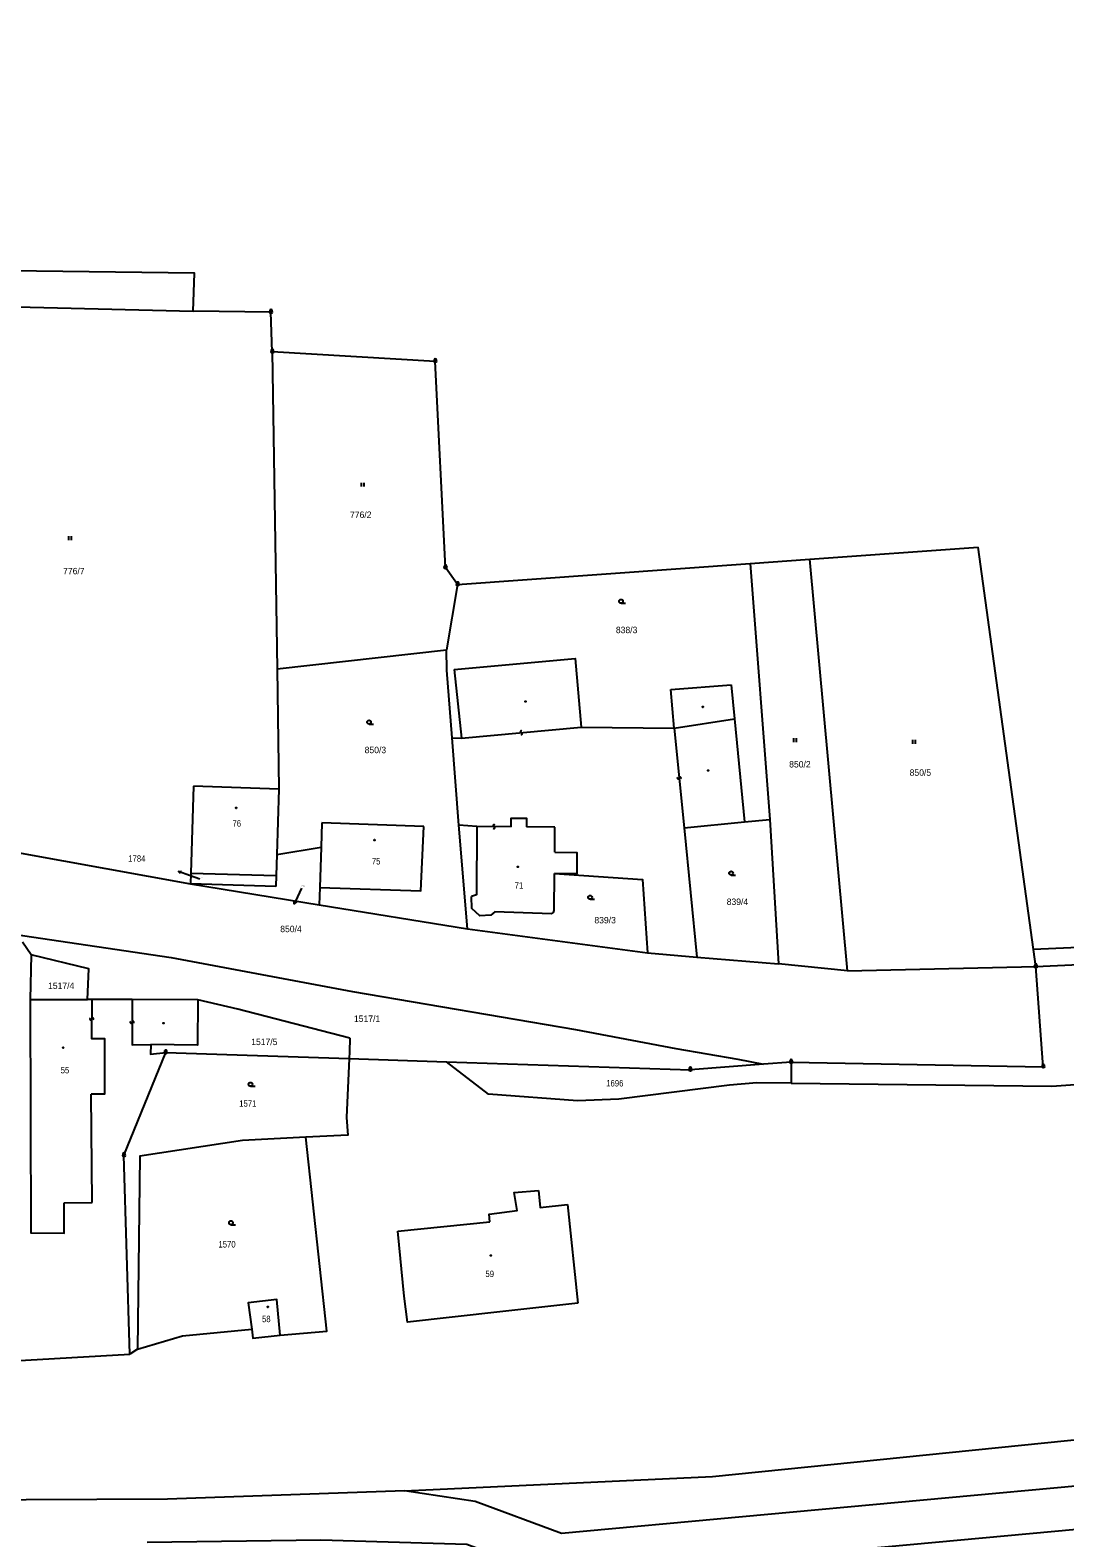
# Model space of a CAD drawing. Extents: x -873052 to -871788, y -1075760 to -1074911.
# Drawn here: x -872787.8 to -872666.9, y -1075585.9 to -1075409.8 of the extents above; entities that cross this region are included whole.
import ezdxf
from ezdxf.enums import TextEntityAlignment as Align

# ---------------------------------------------------------------- set-up
doc = ezdxf.new("R2010")
doc.units = 0
doc.header["$LTSCALE"] = 0.3
for name, color, linetype, lineweight in [('1', 7, 'Continuous', 25), ('16', 7, 'Continuous', 25), ('24', 7, 'Continuous', 25), ('25', 7, 'Continuous', 25), ('4', 7, 'Continuous', 25)]:
    doc.layers.add(name, color=color, linetype=linetype, lineweight=lineweight)
doc.layers.add('18', color=7, linetype='Continuous')
doc.layers.add('19', color=7, linetype='Continuous')

msp = doc.modelspace()

# ---------------------------------------------------------------- linework, layer by layer
at = {"layer": '1'}
for p, q in [((-872696.69, -1075471.56), (-872677.04, -1075470.14)), ((-872670.56, -1075517.14), (-872677.04, -1075470.14)), ((-872692.28, -1075519.65), (-872696.69, -1075471.56)), ((-872737.86, -1075474.53), (-872739.28, -1075472.52)), ((-872703.67, -1075472.06), (-872701.36, -1075501.95)), ((-872737.86, -1075474.53), (-872739.17, -1075482.16)), ((-872758.96, -1075484.35), (-872739.17, -1075482.16)), ((-872739.14, -1075484.53), (-872739.17, -1075482.16)), ((-872738.25, -1075484.46), (-872737.42, -1075492.47)), ((-872712.96, -1075486.77), (-872705.89, -1075486.23)), ((-872712.54, -1075491.29), (-872712.96, -1075486.77)), ((-872705.89, -1075486.23), (-872705.52, -1075490.21)), ((-872705.52, -1075490.21), (-872704.33, -1075502.24)), ((-872738.5, -1075492.43), (-872737.42, -1075492.47)), ((-872758.75, -1075498.42), (-872768.72, -1075498.07)), ((-872741.79, -1075502.77), (-872753.73, -1075502.35)), ((-872735.6, -1075502.78), (-872737.72, -1075502.61)), ((-872711.4, -1075502.94), (-872704.33, -1075502.24)), ((-872711.4, -1075502.94), (-872709.91, -1075518.03)), ((-872704.33, -1075502.24), (-872701.36, -1075501.95)), ((-872701.36, -1075501.95), (-872700.35, -1075518.83)), ((-872758.98, -1075506.05), (-872753.82, -1075505.2)), ((-872769.03, -1075508.22), (-872759.05, -1075508.52)), ((-872759.05, -1075508.52), (-872759.09, -1075509.78)), ((-872726.58, -1075512.61), (-872726.53, -1075508.28)), ((-872759.09, -1075509.78), (-872769.07, -1075509.49)), ((-872753.98, -1075509.9), (-872754.05, -1075511.93)), ((-872736.7, -1075514.75), (-872715.67, -1075517.55)), ((-872787.7, -1075517.76), (-872788.73, -1075516.3)), ((-872692.28, -1075519.65), (-872700.35, -1075518.83)), ((-872692.28, -1075519.65), (-872670.29, -1075519.13)), ((-872776.86, -1075541.21), (-872771.97, -1075529.2)), ((-872771.97, -1075529.2), (-872750.52, -1075529.9)), ((-872750.52, -1075529.9), (-872739.15, -1075530.28)), ((-872705.1, -1075529.95), (-872702.1, -1075530.55)), ((-872739.15, -1075530.28), (-872710.66, -1075531.21)), ((-872776.18, -1075564.42), (-872776.86, -1075541.21)), ((-872725.01, -1075546.94), (-872723.83, -1075558.45)), ((-872744.83, -1075550.06), (-872734.09, -1075548.95)), ((-872744.11, -1075557.66), (-872744.83, -1075550.06)), ((-872723.83, -1075558.45), (-872732.92, -1075559.47)), ((-872791.77, -1075565.32), (-872776.18, -1075564.42))]:
    msp.add_line(p, q, dxfattribs=at)
for points in [[(-872670.29, -1075519.13), (-872603.67, -1075516.06), (-872570.99, -1075513.32), (-872551.67, -1075511.35), (-872538.38, -1075509.27), (-872519.75, -1075503.32), (-872512.06, -1075500.18), (-872477.67, -1075483.87), (-872434.28, -1075461.99), (-872418.27, -1075453.02), (-872406.07, -1075444.11), (-872388.59, -1075428.17), (-872372.28, -1075414.6), (-872357.84, -1075404.1), (-872302.51, -1075368.91), (-872288.48, -1075362.95), (-872276.38, -1075357.94), (-872254.7, -1075350.33), (-872243.27, -1075347.56)], [(-872759.52, -1075447.35), (-872759.67, -1075442.71), (-872768.77, -1075442.57), (-872768.62, -1075438.14), (-872808.66, -1075437.63)], [(-872829.27, -1075441.71), (-872808.47, -1075441.61), (-872768.77, -1075442.57)], [(-872759.52, -1075447.35), (-872758.96, -1075484.35), (-872758.75, -1075498.42)], [(-872739.28, -1075472.52), (-872740.47, -1075448.45), (-872759.52, -1075447.35)], [(-872737.86, -1075474.53), (-872703.67, -1075472.06), (-872696.69, -1075471.56)], [(-872824.32, -1075473.16), (-872808.58, -1075474.44), (-872804.87, -1075502.99), (-872804.17, -1075503.12), (-872769.07, -1075509.49)], [(-872738.25, -1075484.46), (-872724.14, -1075483.16), (-872723.41, -1075491.19), (-872712.54, -1075491.29)], [(-872736.7, -1075514.75), (-872737.72, -1075502.61), (-872738.5, -1075492.43), (-872739.14, -1075484.53)], [(-872768.72, -1075498.07), (-872769.03, -1075508.22), (-872769.07, -1075509.49)], [(-872758.75, -1075498.42), (-872758.98, -1075506.05), (-872759.05, -1075508.52)], [(-872753.73, -1075502.35), (-872753.82, -1075505.2), (-872753.98, -1075509.9)], [(-872753.98, -1075509.9), (-872742.17, -1075510.3), (-872741.79, -1075502.77)], [(-872735.6, -1075502.78), (-872735.66, -1075510.75), (-872736.22, -1075510.95)], [(-872726.53, -1075508.28), (-872716.25, -1075508.97), (-872715.67, -1075517.55)], [(-872769.07, -1075509.49), (-872754.05, -1075511.93), (-872736.7, -1075514.75)], [(-872564.93, -1075510.69), (-872571.18, -1075511.33), (-872603.8, -1075514.06), (-872633.81, -1075515.5), (-872670.56, -1075517.14)], [(-872726.87, -1075512.99), (-872733.52, -1075512.76), (-872733.96, -1075513.16), (-872735.27, -1075513.21), (-872736.18, -1075512.36), (-872736.22, -1075510.95)], [(-872726.87, -1075512.99), (-872726.66, -1075512.84), (-872726.58, -1075512.61)], [(-872794.34, -1075514.5), (-872788.73, -1075515.53), (-872771.33, -1075518.1), (-872750.13, -1075522.07), (-872724.09, -1075526.5), (-872712.35, -1075528.71), (-872705.1, -1075529.95)], [(-872780.62, -1075522.99), (-872781.11, -1075522.99), (-872780.94, -1075519.4), (-872787.7, -1075517.76), (-872787.81, -1075522.98), (-872781.11, -1075522.99)], [(-872715.67, -1075517.55), (-872709.91, -1075518.03), (-872700.35, -1075518.83)], [(-872698.88, -1075530.3), (-872669.42, -1075530.84), (-872670.29, -1075519.13), (-872670.56, -1075517.14)], [(-872768.24, -1075523.05), (-872775.88, -1075523), (-872780.62, -1075522.99)], [(-872750.44, -1075527.52), (-872763.55, -1075524.14), (-872768.24, -1075523.05), (-872768.27, -1075528.34), (-872773.73, -1075528.26)], [(-872698.89, -1075532.77), (-872668.42, -1075533.1), (-872643.77, -1075531.38), (-872643.97, -1075527.32), (-872613.91, -1075525.57), (-872613.56, -1075528.66), (-872543.08, -1075522.8)], [(-872773.73, -1075528.26), (-872773.75, -1075529.37), (-872771.97, -1075529.2)], [(-872750.44, -1075527.52), (-872750.51, -1075529.12), (-872750.52, -1075529.9)], [(-872750.52, -1075529.9), (-872750.83, -1075536.77), (-872750.71, -1075538.83), (-872755.59, -1075539.08), (-872763, -1075539.48), (-872774.99, -1075541.31), (-872775.28, -1075563.83), (-872776.18, -1075564.42)], [(-872698.88, -1075530.3), (-872698.89, -1075532.77), (-872702.9, -1075532.73), (-872706.07, -1075533), (-872719.01, -1075534.62), (-872723.85, -1075534.83), (-872734.26, -1075534.05), (-872739.15, -1075530.28)], [(-872698.88, -1075530.3), (-872702.1, -1075530.55), (-872710.66, -1075531.21)], [(-872775.28, -1075563.83), (-872770.01, -1075562.3), (-872761.92, -1075561.5), (-872761.78, -1075562.55), (-872758.59, -1075562.22), (-872753.14, -1075561.73), (-872755.59, -1075539.08)], [(-872734.09, -1075548.95), (-872734.17, -1075548.06), (-872730.91, -1075547.65), (-872731.26, -1075545.52), (-872728.42, -1075545.3)], [(-872728.42, -1075545.3), (-872728.22, -1075547.31), (-872725.01, -1075546.94)], [(-872758.59, -1075562.22), (-872758.99, -1075558.03), (-872762.32, -1075558.42), (-872761.92, -1075561.5)], [(-872732.92, -1075559.47), (-872743.72, -1075560.68), (-872744.11, -1075557.66)], [(-872774.15, -1075586.39), (-872753.85, -1075586.1), (-872736.78, -1075586.6), (-872726.39, -1075590.46), (-872640.59, -1075582.55), (-872588.07, -1075576.45), (-872574.25, -1075574.02)], [(-872744.07, -1075580.4), (-872771.76, -1075581.38), (-872796.59, -1075581.46), (-872806.52, -1075582.41), (-872841.24, -1075589.52), (-872854.93, -1075590.98), (-872855.87, -1075594.41), (-872882.38, -1075602.48), (-872900.74, -1075606.59), (-872949.7, -1075610.64)]]:
    msp.add_lwpolyline(points, dxfattribs=at)
msp.add_lwpolyline([(-872509.66, -1075552.26), (-872556.08, -1075562.43), (-872561.37, -1075565.16), (-872575.37, -1075569.14), (-872588.79, -1075571.5), (-872641.1, -1075577.58), (-872725.73, -1075585.37), (-872735.81, -1075581.63), (-872744.07, -1075580.4), (-872708.06, -1075578.71), (-872660.84, -1075573.94), (-872594.85, -1075565.87), (-872551.8, -1075558.86)], close=True, dxfattribs=at)
at = {"layer": '16'}
for p, q in [((-872769.62, -1075508.35), (-872770.467, -1075508.048)), ((-872767.99, -1075508.93), (-872769.62, -1075508.35)), ((-872756.11, -1075509.98), (-872756.58, -1075510.99)), ((-872756.58, -1075510.99), (-872756.96, -1075511.805))]:
    msp.add_line(p, q, dxfattribs=at)
for points in [[(-872770.235, -1075508.29), (-872770.467, -1075508.048), (-872770.134, -1075508.007)], [(-872756.697, -1075511.596), (-872756.96, -1075511.805), (-872756.969, -1075511.47)]]:
    msp.add_lwpolyline(points, dxfattribs=at)
at = {"layer": '24'}
for centre, radius in [((-872759.6695, -1075442.7095), 0.1505), ((-872759.6695, -1075442.7095), 0.00652), ((-872759.5195, -1075447.3495), 0.1505), ((-872759.5195, -1075447.3495), 0.00652), ((-872740.4695, -1075448.4495), 0.1505), ((-872740.4695, -1075448.4495), 0.00652), ((-872739.2795, -1075472.5195), 0.1505), ((-872739.2795, -1075472.5195), 0.00652), ((-872737.8595, -1075474.5295), 0.1505), ((-872737.8595, -1075474.5295), 0.00652), ((-872670.2895, -1075519.1295), 0.1505), ((-872670.2895, -1075519.1295), 0.00652), ((-872771.9695, -1075529.1995), 0.1505), ((-872771.9695, -1075529.1995), 0.00652), ((-872710.6595, -1075531.2095), 0.1505), ((-872710.6595, -1075531.2095), 0.00652), ((-872698.8795, -1075530.2995), 0.1505), ((-872698.8795, -1075530.2995), 0.00652), ((-872669.4195, -1075530.8395), 0.1505), ((-872669.4195, -1075530.8395), 0.00652), ((-872776.8595, -1075541.2095), 0.1505), ((-872776.8595, -1075541.2095), 0.00652)]:
    msp.add_circle(centre, radius, dxfattribs=at)
for centre in [(-872759.6696, -1075442.5401), (-872759.5196, -1075447.1801), (-872740.4696, -1075448.2801), (-872739.2796, -1075472.3501), (-872737.8596, -1075474.3601), (-872670.2896, -1075518.9601), (-872771.9696, -1075529.0301), (-872698.8796, -1075530.1301), (-872710.6596, -1075531.0401), (-872669.4196, -1075530.6701), (-872776.8596, -1075541.0401)]:
    msp.add_arc(centre, 0.1311, 328.53402, 210.28963, dxfattribs=at)
at = {"layer": '25'}
for p, q in [((-872749.085, -1075463.079), (-872749.085, -1075462.629)), ((-872748.774, -1075463.079), (-872748.774, -1075462.629)), ((-872783.295, -1075469.319), (-872783.295, -1075468.869)), ((-872782.984, -1075469.319), (-872782.984, -1075468.869)), ((-872718.76, -1075476.71), (-872718.234, -1075476.71)), ((-872748.21, -1075490.82), (-872747.684, -1075490.82)), ((-872698.575, -1075492.919), (-872698.575, -1075492.469)), ((-872698.264, -1075492.919), (-872698.264, -1075492.469)), ((-872684.665, -1075493.129), (-872684.665, -1075492.679)), ((-872684.354, -1075493.129), (-872684.354, -1075492.679)), ((-872705.9, -1075508.46), (-872705.374, -1075508.46)), ((-872722.38, -1075511.29), (-872721.854, -1075511.29)), ((-872762.06, -1075533.13), (-872761.534, -1075533.13)), ((-872764.35, -1075549.3), (-872763.824, -1075549.3))]:
    msp.add_line(p, q, dxfattribs=at)
for centre, radius in [((-872718.7595, -1075476.4845), 0.2255), ((-872729.9395, -1075488.1795), 0.0525), ((-872709.1995, -1075488.8195), 0.0525), ((-872748.2095, -1075490.5945), 0.2255), ((-872708.5695, -1075496.2395), 0.0525), ((-872763.7495, -1075500.6195), 0.0525), ((-872747.5795, -1075504.3695), 0.0525), ((-872730.8295, -1075507.4995), 0.0525), ((-872705.8995, -1075508.2345), 0.2255), ((-872722.3795, -1075511.0645), 0.2255), ((-872772.2295, -1075525.7595), 0.0525), ((-872783.9495, -1075528.6195), 0.0525), ((-872762.0595, -1075532.9045), 0.2255), ((-872764.3495, -1075549.0745), 0.2255), ((-872733.9695, -1075552.8995), 0.0525), ((-872760.0495, -1075558.9095), 0.0525)]:
    msp.add_circle(centre, radius, dxfattribs=at)
for centre, radius, start, end in [((-872730.4283, -1075491.7198), 0.1105, 42.56866, 274.16182), ((-872730.4109, -1075491.94), 0.1104, 222.79917, 95.54836), ((-872712.08, -1075497.1291), 0.1104, 132.79846, 4.68031), ((-872711.86, -1075497.1099), 0.1104, 311.88135, 185.1959), ((-872733.6078, -1075502.6792), 0.1108, 36.55993, 268.1437), ((-872733.6114, -1075502.9003), 0.1103, 216.54948, 89.47986), ((-872780.7405, -1075525.2582), 0.1105, 127.28534, 358.96121), ((-872780.5195, -1075525.2608), 0.1105, 305.9788, 179.48057), ((-872776.0105, -1075525.6472), 0.1105, 127.28534, 358.44061), ((-872775.7896, -1075525.651), 0.1104, 306.97282, 179.48057)]:
    msp.add_arc(centre, radius, start, end, dxfattribs=at)
at = {"layer": '4'}
for p, q in [((-872737.42, -1075492.47), (-872723.41, -1075491.19)), ((-872712.54, -1075491.29), (-872705.52, -1075490.21)), ((-872712.54, -1075491.29), (-872711.4, -1075502.94)), ((-872731.62, -1075502.81), (-872735.6, -1075502.78)), ((-872726.49, -1075502.85), (-872729.83, -1075502.82)), ((-872726.51, -1075505.79), (-872726.49, -1075502.85)), ((-872780.57, -1075546.7), (-872780.69, -1075534.04)), ((-872783.86, -1075546.76), (-872780.57, -1075546.7))]:
    msp.add_line(p, q, dxfattribs=at)
for points in [[(-872731.62, -1075502.81), (-872731.61, -1075501.81), (-872729.82, -1075501.83), (-872729.83, -1075502.82)], [(-872726.51, -1075505.79), (-872723.92, -1075505.81), (-872723.94, -1075508.3), (-872726.53, -1075508.28)], [(-872787.81, -1075522.98), (-872787.75, -1075550.26), (-872783.83, -1075550.29), (-872783.86, -1075546.76)], [(-872780.62, -1075522.99), (-872780.63, -1075527.54), (-872779.13, -1075527.54), (-872779.14, -1075534.04), (-872780.69, -1075534.04)], [(-872775.88, -1075523), (-872775.91, -1075528.29), (-872773.73, -1075528.26)]]:
    msp.add_lwpolyline(points, dxfattribs=at)

# ---------------------------------------------------------------- texts
at = {"layer": '16', "width": 0.9}
msp.add_text('1784', height=0.75, dxfattribs=at).set_placement((-872775.3495, -1075506.9), align=Align.CENTER)
at = {"layer": '16'}
msp.add_text('850/4', height=0.75, dxfattribs=at).set_placement((-872756.08, -1075515.13), align=Align.RIGHT)
at = {"layer": '18'}
for s, height, p in [('776/2', 0.75, (-872749.1795, -1075466.74)), ('776/7', 0.75, (-872782.7095, -1075473.32)), ('838/3', 0.75, (-872718.1095, -1075480.2)), ('850/3', 0.75, (-872747.4695, -1075494.22)), ('850/2', 0.75, (-872697.8595, -1075495.89)), ('850/5', 0.75, (-872683.7795, -1075496.86)), ('850/4', 0.1, (-872755.9095, -1075509.78)), ('839/4', 0.75, (-872705.1595, -1075511.95)), ('839/3', 0.75, (-872720.6195, -1075514.1)), ('1517/4', 0.75, (-872784.1895, -1075521.76)), ('1517/1', 0.75, (-872748.4395, -1075525.61)), ('1517/5', 0.75, (-872760.4495, -1075528.32))]:
    msp.add_text(s, height=height, dxfattribs=at).set_placement(p, align=Align.CENTER)
at = {"layer": '18', "width": 0.9}
for s, height, p in [('1784', 0.1, (-872767.79, -1075508.73)), ('1696', 0.75, (-872719.4895, -1075533.155)), ('1571', 0.75, (-872762.3795, -1075535.515)), ('1570', 0.75, (-872764.8095, -1075551.965))]:
    msp.add_text(s, height=height, dxfattribs=at).set_placement(p, align=Align.CENTER)
at = {"layer": '19', "width": 0.9}
for s, p in [('76', (-872763.6695, -1075502.8)), ('75', (-872747.3795, -1075507.22)), ('71', (-872730.6895, -1075510.04)), ('55', (-872783.7495, -1075531.62)), ('59', (-872734.1095, -1075555.415)), ('58', (-872760.2195, -1075560.685))]:
    msp.add_text(s, height=0.75, dxfattribs=at).set_placement(p, align=Align.CENTER)

doc.saveas('drawing.dxf')
